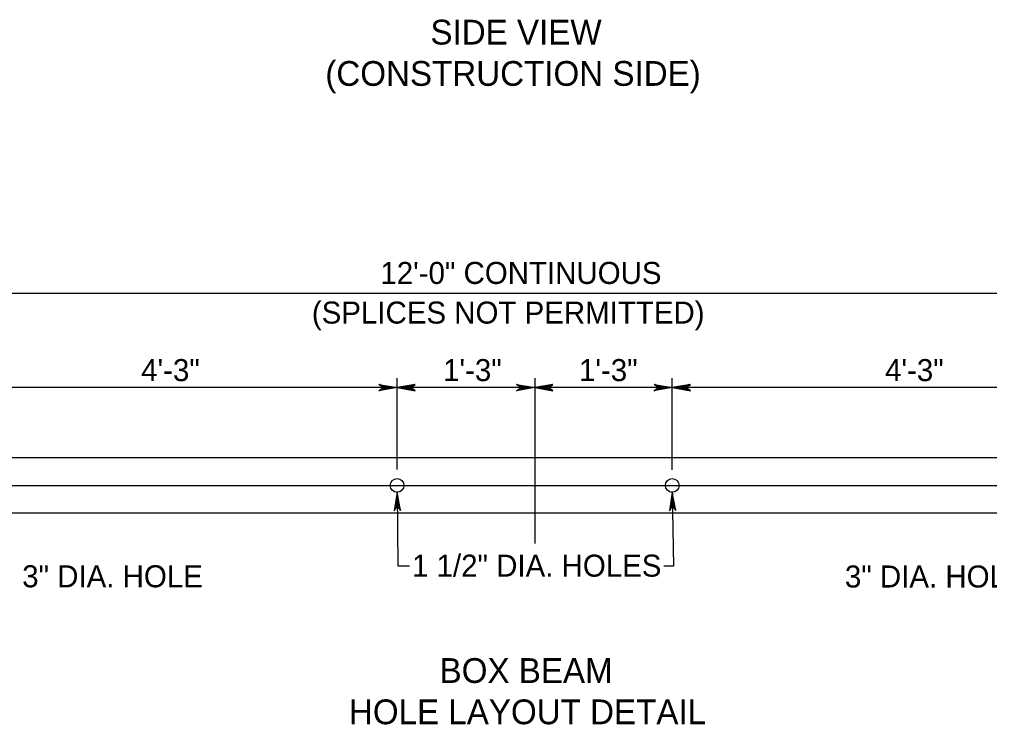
# Model space of a CAD drawing. Extents: x 499881 to 500993, y 499985 to 500645.
# Drawn here: x 500108.7 to 500285, y 500387.1 to 500515.2 of the extents above; entities that cross this region are included whole.
import ezdxf

# ---------------------------------------------------------------- set-up
doc = ezdxf.new("R2010")
doc.units = 0
for name, color, linetype in [('2', 7, 'Continuous'), ('3', 7, 'Continuous'), ('5', 7, 'Continuous')]:
    doc.layers.add(name, color=color, linetype=linetype)

msp = doc.modelspace()

# ---------------------------------------------------------------- linework, layer by layer
at = {"layer": '2'}
for points in [[(500177.33, 500448.3), (500174, 500447.71), (500174.8, 500448.3), (500174.02, 500448.88), (500177.33, 500448.3), (500177.11, 500448.31), (500174.1, 500447.76), (500174.86, 500448.31), (500174.15, 500448.83), (500176.99, 500448.32), (500176.88, 500448.3), (500174.3, 500447.84), (500174.88, 500448.31), (500174.28, 500448.76), (500176.83, 500448.3), (500176.71, 500448.32), (500174.46, 500447.91), (500174.9, 500448.3), (500174.45, 500448.71), (500176.39, 500448.32), (500176.21, 500448.32), (500174.63, 500448), (500174.94, 500448.29), (500174.6, 500448.62), (500176.17, 500448.3), (500176, 500448.29), (500174.81, 500448.09), (500175.04, 500448.32), (500174.79, 500448.55), (500175.83, 500448.3), (500175.67, 500448.28), (500174.95, 500448.15), (500175.07, 500448.31), (500174.88, 500448.49), (500175.58, 500448.3), (500175.11, 500448.19), (500175.18, 500448.32), (500174.98, 500448.45), (500175.46, 500448.32), (500175.16, 500448.24), (500175.28, 500448.34), (500175.14, 500448.4), (500175.28, 500448.31), (500175.21, 500448.29)], [(500177.33, 500448.3), (500180.65, 500447.71), (500179.86, 500448.3), (500180.63, 500448.88), (500177.33, 500448.3), (500177.55, 500448.31), (500180.56, 500447.76), (500179.79, 500448.31), (500180.5, 500448.83), (500177.67, 500448.32), (500177.78, 500448.3), (500180.36, 500447.84), (500179.78, 500448.31), (500180.37, 500448.76), (500177.83, 500448.3), (500177.94, 500448.32), (500180.19, 500447.91), (500179.75, 500448.3), (500180.2, 500448.71), (500178.26, 500448.32), (500178.45, 500448.32), (500180.03, 500448), (500179.72, 500448.29), (500180.05, 500448.62), (500178.48, 500448.3), (500178.66, 500448.29), (500179.84, 500448.09), (500179.62, 500448.32), (500179.86, 500448.55), (500178.82, 500448.3), (500178.99, 500448.28), (500179.7, 500448.15), (500179.58, 500448.31), (500179.78, 500448.49), (500179.08, 500448.3), (500179.54, 500448.19), (500179.47, 500448.32), (500179.68, 500448.45), (500179.19, 500448.32), (500179.5, 500448.24), (500179.37, 500448.34), (500179.52, 500448.4), (500179.37, 500448.31), (500179.45, 500448.29)], [(500202.33, 500448.3), (500199, 500447.71), (500199.8, 500448.3), (500199.02, 500448.88), (500202.33, 500448.3), (500202.11, 500448.31), (500199.1, 500447.76), (500199.86, 500448.31), (500199.15, 500448.83), (500201.99, 500448.32), (500201.88, 500448.3), (500199.3, 500447.84), (500199.88, 500448.31), (500199.28, 500448.76), (500201.83, 500448.3), (500201.71, 500448.32), (500199.46, 500447.91), (500199.9, 500448.3), (500199.45, 500448.71), (500201.39, 500448.32), (500201.21, 500448.32), (500199.63, 500448), (500199.94, 500448.29), (500199.6, 500448.62), (500201.17, 500448.3), (500201, 500448.29), (500199.81, 500448.09), (500200.04, 500448.32), (500199.79, 500448.55), (500200.83, 500448.3), (500200.66, 500448.28), (500199.95, 500448.15), (500200.07, 500448.31), (500199.88, 500448.49), (500200.58, 500448.3), (500200.11, 500448.19), (500200.18, 500448.32), (500199.98, 500448.45), (500200.46, 500448.32), (500200.16, 500448.24), (500200.28, 500448.34), (500200.14, 500448.4), (500200.28, 500448.31), (500200.21, 500448.29)], [(500202.33, 500448.3), (500205.65, 500447.71), (500204.86, 500448.3), (500205.63, 500448.88), (500202.33, 500448.3), (500202.55, 500448.31), (500205.56, 500447.76), (500204.79, 500448.31), (500205.5, 500448.83), (500202.67, 500448.32), (500202.78, 500448.3), (500205.36, 500447.84), (500204.78, 500448.31), (500205.37, 500448.76), (500202.83, 500448.3), (500202.94, 500448.32), (500205.19, 500447.91), (500204.75, 500448.3), (500205.2, 500448.71), (500203.26, 500448.32), (500203.45, 500448.32), (500205.03, 500448), (500204.72, 500448.29), (500205.05, 500448.62), (500203.48, 500448.3), (500203.66, 500448.29), (500204.84, 500448.09), (500204.62, 500448.32), (500204.86, 500448.55), (500203.82, 500448.3), (500203.99, 500448.28), (500204.7, 500448.15), (500204.58, 500448.31), (500204.78, 500448.49), (500204.07, 500448.3), (500204.54, 500448.19), (500204.47, 500448.32), (500204.68, 500448.45), (500204.19, 500448.32), (500204.5, 500448.24), (500204.37, 500448.34), (500204.52, 500448.4), (500204.37, 500448.31), (500204.45, 500448.29)], [(500227.33, 500448.3), (500224, 500447.71), (500224.8, 500448.3), (500224.02, 500448.88), (500227.33, 500448.3), (500227.11, 500448.31), (500224.1, 500447.76), (500224.86, 500448.31), (500224.15, 500448.83), (500226.99, 500448.32), (500226.88, 500448.3), (500224.3, 500447.84), (500224.88, 500448.31), (500224.28, 500448.76), (500226.83, 500448.3), (500226.72, 500448.32), (500224.46, 500447.91), (500224.9, 500448.3), (500224.45, 500448.71), (500226.39, 500448.32), (500226.21, 500448.32), (500224.63, 500448), (500224.94, 500448.29), (500224.6, 500448.62), (500226.17, 500448.3), (500226, 500448.29), (500224.81, 500448.09), (500225.04, 500448.32), (500224.79, 500448.55), (500225.83, 500448.3), (500225.67, 500448.28), (500224.95, 500448.15), (500225.07, 500448.31), (500224.88, 500448.49), (500225.58, 500448.3), (500225.11, 500448.19), (500225.18, 500448.32), (500224.98, 500448.45), (500225.46, 500448.32), (500225.16, 500448.24), (500225.28, 500448.34), (500225.14, 500448.4), (500225.28, 500448.31), (500225.21, 500448.29)], [(500227.33, 500448.3), (500230.65, 500447.71), (500229.86, 500448.3), (500230.63, 500448.88), (500227.33, 500448.3), (500227.55, 500448.31), (500230.56, 500447.76), (500229.79, 500448.31), (500230.5, 500448.83), (500227.67, 500448.32), (500227.78, 500448.3), (500230.36, 500447.84), (500229.78, 500448.31), (500230.37, 500448.76), (500227.83, 500448.3), (500227.94, 500448.32), (500230.19, 500447.91), (500229.75, 500448.3), (500230.2, 500448.71), (500228.26, 500448.32), (500228.45, 500448.32), (500230.03, 500448), (500229.72, 500448.29), (500230.05, 500448.62), (500228.48, 500448.3), (500228.66, 500448.29), (500229.84, 500448.09), (500229.62, 500448.32), (500229.86, 500448.55), (500228.82, 500448.3), (500228.99, 500448.28), (500229.7, 500448.15), (500229.58, 500448.31), (500229.78, 500448.49), (500229.08, 500448.3), (500229.54, 500448.19), (500229.47, 500448.32), (500229.68, 500448.45), (500229.19, 500448.32), (500229.5, 500448.24), (500229.37, 500448.34), (500229.52, 500448.4), (500229.37, 500448.31), (500229.45, 500448.29)], [(500177.33, 500429.28), (500176.81, 500425.94), (500177.38, 500426.75), (500177.98, 500425.98), (500177.33, 500429.28), (500177.34, 500429.06), (500176.85, 500426.03), (500177.39, 500426.81), (500177.93, 500426.12), (500177.35, 500428.94), (500177.34, 500428.83), (500176.94, 500426.24), (500177.39, 500426.83), (500177.85, 500426.24), (500177.34, 500428.77), (500177.36, 500428.66), (500177, 500426.4), (500177.38, 500426.85), (500177.8, 500426.41), (500177.36, 500428.34), (500177.37, 500428.16), (500177.08, 500426.57), (500177.37, 500426.88), (500177.71, 500426.56), (500177.35, 500428.12), (500177.35, 500427.94), (500177.17, 500426.75), (500177.39, 500426.99), (500177.63, 500426.74), (500177.36, 500427.78), (500177.35, 500427.61), (500177.23, 500426.9), (500177.38, 500427.02), (500177.57, 500426.83), (500177.37, 500427.53), (500177.27, 500427.06), (500177.39, 500427.13), (500177.52, 500426.93), (500177.39, 500427.41), (500177.32, 500427.1), (500177.41, 500427.23), (500177.48, 500427.09), (500177.38, 500427.23), (500177.36, 500427.16)], [(500227.33, 500429.28), (500226.81, 500425.94), (500227.38, 500426.75), (500227.97, 500425.98), (500227.33, 500429.28), (500227.34, 500429.06), (500226.85, 500426.04), (500227.38, 500426.81), (500227.92, 500426.11), (500227.35, 500428.94), (500227.34, 500428.83), (500226.93, 500426.24), (500227.38, 500426.83), (500227.85, 500426.24), (500227.34, 500428.77), (500227.36, 500428.66), (500226.99, 500426.4), (500227.37, 500426.85), (500227.79, 500426.41), (500227.36, 500428.34), (500227.37, 500428.16), (500227.07, 500426.57), (500227.37, 500426.88), (500227.7, 500426.56), (500227.35, 500428.12), (500227.34, 500427.94), (500227.16, 500426.75), (500227.39, 500426.99), (500227.62, 500426.74), (500227.36, 500427.78), (500227.34, 500427.61), (500227.22, 500426.9), (500227.38, 500427.02), (500227.56, 500426.83), (500227.36, 500427.53), (500227.26, 500427.06), (500227.39, 500427.13), (500227.52, 500426.93), (500227.38, 500427.41), (500227.31, 500427.1), (500227.41, 500427.23), (500227.47, 500427.09), (500227.37, 500427.23), (500227.36, 500427.16)]]:
    msp.add_lwpolyline(points, dxfattribs=at)
at = {"layer": '3'}
for p, q in [((500322.33, 500465.37), (500082.33, 500465.37)), ((500177.33, 500433.4), (500177.33, 500449.99)), ((500227.33, 500433.38), (500227.33, 500449.99)), ((500177.33, 500448.3), (500092.34, 500448.3)), ((500202.33, 500448.3), (500177.33, 500448.3)), ((500227.33, 500448.3), (500202.33, 500448.3)), ((500312.36, 500448.3), (500227.33, 500448.3)), ((500322.33, 500435.53), (500082.33, 500435.53)), ((500177.33, 500429.28), (500177.47, 500415.94)), ((500227.33, 500429.28), (500227.54, 500415.85)), ((500082.33, 500425.53), (500322.33, 500425.53)), ((500177.47, 500415.94), (500179.6, 500415.94)), ((500227.54, 500415.85), (500225.8, 500415.85))]:
    msp.add_line(p, q, dxfattribs=at)
for centre in [(500177.33, 500430.53), (500227.33, 500430.53)]:
    msp.add_circle(centre, 1.25, dxfattribs=at)
at = {"layer": '5'}
for p, q in [((500202.33, 500449.99), (500202.33, 500420.01)), ((500072.33, 500430.53), (500332.33, 500430.53))]:
    msp.add_line(p, q, dxfattribs=at)

# ---------------------------------------------------------------- texts
at = {"layer": '3'}
for s, p in [('12\'-0" CONTINUOUS', (500174.3, 500467.12)), ('(SPLICES NOT PERMITTED)', (500161.86, 500459.92)), ('4\'-3"', (500130.85, 500449.47)), ('1\'-3"', (500185.69, 500449.47)), ('1\'-3"', (500210.38, 500449.47)), ('4\'-3"', (500265.97, 500449.47)), ('1 1/2" DIA. HOLES', (500180.05, 500413.96)), ('3" DIA. HOLE', (500109.24, 500412.03)), ('3" DIA. HOLE', (500258.68, 500411.99))]:
    msp.add_text(s, height=4, dxfattribs=at).set_placement(p)
at = {"layer": '5'}
for s, p in [('SIDE VIEW', (500183.4, 500510.6)), ('(CONSTRUCTION SIDE)', (500164.3, 500503.1)), ('BOX BEAM', (500185.06, 500394.66)), ('HOLE LAYOUT DETAIL', (500168.59, 500387.16))]:
    msp.add_text(s, height=4.5, dxfattribs=at).set_placement(p)

doc.saveas('drawing.dxf')
